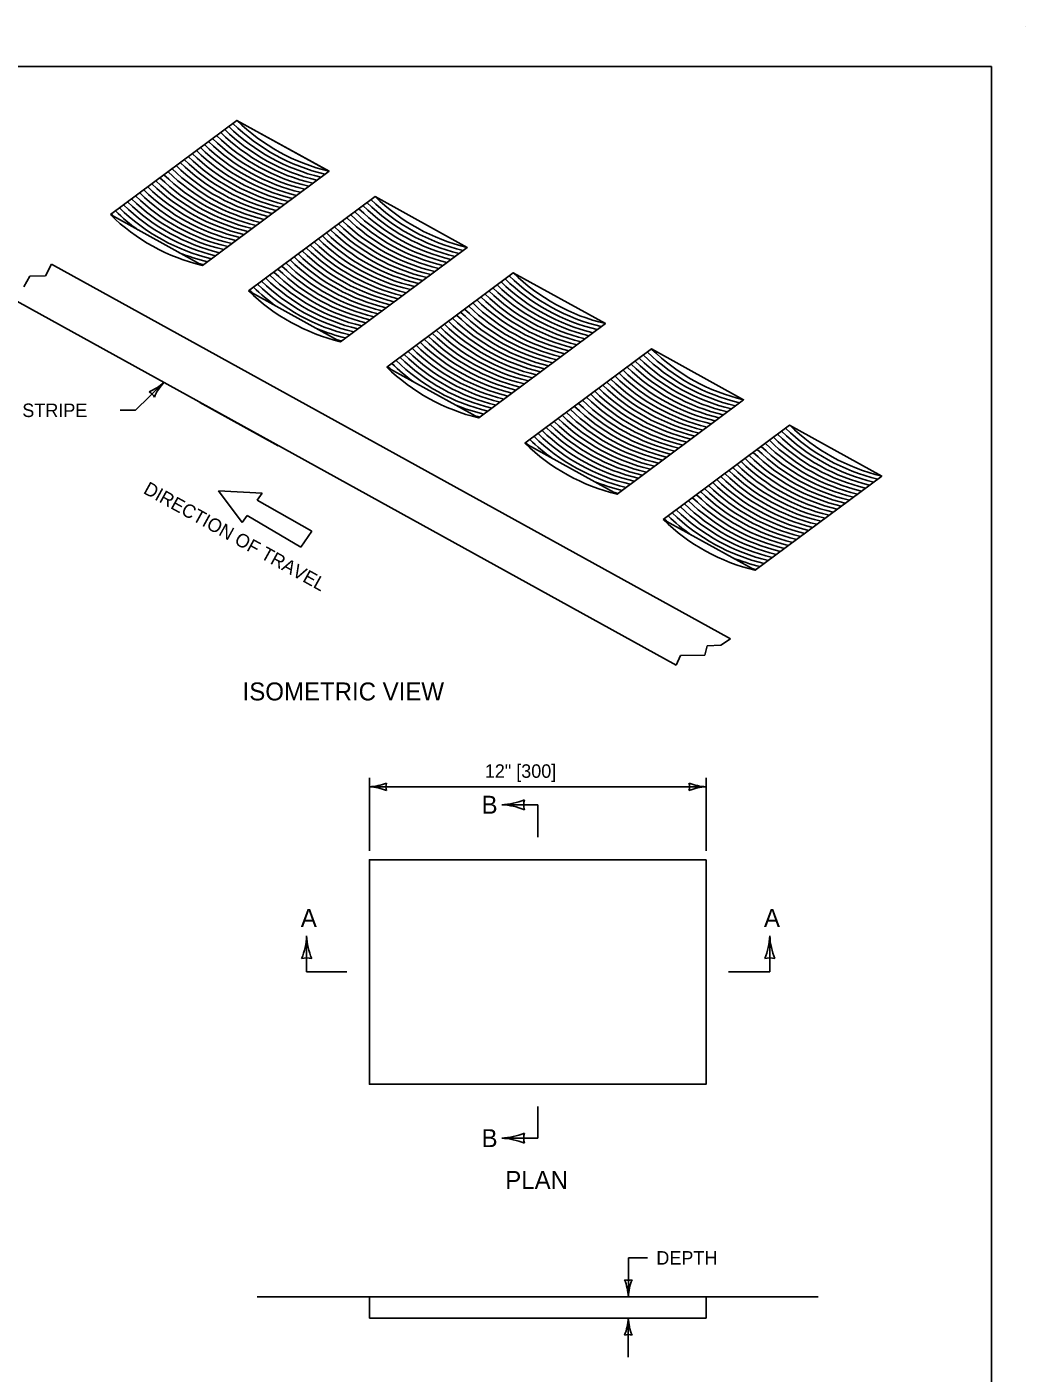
# Model space of a CAD drawing. Extents: x 49991.4 to 50021, y 49987.6 to 50011.4.
# Drawn here: x 50012.45 to 50016.9, y 49993.18 to 49999.18 of the extents above; entities that cross this region are included whole.
import ezdxf

# ---------------------------------------------------------------- set-up
doc = ezdxf.new("R2010")
doc.units = 0
for name, color, linetype in [('Level 1', 7, 'Continuous'), ('Level 2', 7, 'Continuous'), ('Level 3', 7, 'Continuous'), ('Level 4', 7, 'Continuous'), ('Level 6', 7, 'Continuous')]:
    doc.layers.add(name, color=color, linetype=linetype)

msp = doc.modelspace()

# ---------------------------------------------------------------- linework, layer by layer
at = {"layer": 'Level 1'}
for p, q in [((50016.9001, 49999.1756), (50016.9001, 49999.1756)), ((50013.7983, 49998.5328), (50013.3878, 49998.7591)), ((50014.4143, 49998.1935), (50014.0037, 49998.4198)), ((50012.5625, 49998.1179), (50012.5359, 49998.0661)), ((50015.5869, 49996.45), (50012.5625, 49998.1179)), ((50012.4655, 49998.065), (50012.4382, 49998.018)), ((50012.5359, 49998.0661), (50012.4655, 49998.065)), ((50015.03, 49997.8539), (50014.6195, 49998.0803)), ((50015.3448, 49996.3328), (50012.3203, 49998.0008)), ((50015.6458, 49997.5143), (50015.2353, 49997.7407)), ((50013.223, 49997.5029), (50013.5726, 49997.31)), ((50016.2616, 49997.1747), (50015.8511, 49997.4011)), ((50013.5002, 49997.0984), (50013.306, 49997.109)), ((50013.306, 49997.109), (50013.4121, 49996.9676)), ((50013.4787, 49997.0667), (50013.5002, 49997.0984)), ((50013.7217, 49996.9287), (50013.4787, 49997.0667)), ((50013.4121, 49996.9676), (50013.4333, 49996.9987)), ((50013.4333, 49996.9987), (50013.6726, 49996.8579)), ((50013.6726, 49996.8579), (50013.7217, 49996.9287)), ((50015.5869, 49996.45), (50015.5437, 49996.4217)), ((50015.3643, 49996.3756), (50015.3448, 49996.3328)), ((50015.4727, 49996.3764), (50015.3643, 49996.3756)), ((50015.4833, 49996.4185), (50015.4727, 49996.3764)), ((50015.5437, 49996.4217), (50015.4833, 49996.4185)), ((50013.9786, 49994.4652), (50015.4786, 49994.4652)), ((50013.4786, 49993.5182), (50015.9786, 49993.5182)), ((50013.9786, 49993.4232), (50013.9786, 49993.5182)), ((50015.4786, 49993.5182), (50015.4786, 49993.4232)), ((50013.9786, 49993.4232), (50015.4786, 49993.4232))]:
    msp.add_line(p, q, dxfattribs=at)
for points in [[(49999.3835, 49998.9992), (50016.7501, 49998.9992), (50016.7501, 49987.7988), (49999.3835, 49987.7988)], [(50012.8243, 49998.3392), (50013.2347, 49998.1128), (50013.7985, 49998.533), (50013.388, 49998.7593)], [(50013.44, 49997.9997), (50013.8504, 49997.7733), (50014.4143, 49998.1935), (50014.0037, 49998.4198)], [(50014.0558, 49997.6601), (50014.4662, 49997.4338), (50015.03, 49997.8539), (50014.6195, 49998.0803)], [(50014.6716, 49997.3205), (50015.082, 49997.0943), (50015.6458, 49997.5143), (50015.2353, 49997.7407)], [(50015.2874, 49996.9809), (50015.6978, 49996.7547), (50016.2616, 49997.1747), (50015.8511, 49997.4011)], [(50015.4786, 49995.4652), (50015.4786, 49994.4652), (50013.9786, 49994.4652), (50013.9786, 49995.4652)]]:
    msp.add_lwpolyline(points, close=True, dxfattribs=at)
for centre, radius, start, end in [((50013.9299, 49999.3336), 0.8786, 225.65161, 256.59181), ((50013.9479, 49999.3471), 0.8786, 225.6516, 256.59175), ((50013.966, 49999.3605), 0.8786, 225.65159, 256.59168), ((50013.984, 49999.374), 0.8786, 225.65158, 256.59161), ((50014.0019, 49999.3874), 0.8786, 225.65631, 256.59765), ((50014.0019, 49999.3874), 0.8786, 225.65548, 256.59848), ((50013.8577, 49999.2799), 0.8786, 225.65165, 256.59209), ((50013.8757, 49999.2933), 0.8786, 225.65164, 256.59202), ((50013.8938, 49999.3068), 0.8786, 225.65163, 256.59195), ((50013.9118, 49999.3202), 0.8786, 225.65162, 256.59188), ((50013.7675, 49999.2126), 0.8786, 225.6517, 256.59243), ((50013.7855, 49999.2261), 0.8786, 225.65169, 256.59236), ((50013.8036, 49999.2395), 0.8786, 225.65168, 256.59229), ((50013.8216, 49999.253), 0.8786, 225.65167, 256.59222), ((50013.8397, 49999.2664), 0.8786, 225.65166, 256.59216), ((50013.6953, 49999.1589), 0.8786, 225.65174, 256.5927), ((50013.7134, 49999.1723), 0.8786, 225.65173, 256.59264), ((50013.7314, 49999.1858), 0.8786, 225.65172, 256.59257), ((50013.7495, 49999.1992), 0.8786, 225.65171, 256.5925), ((50013.6051, 49999.0916), 0.8786, 225.65179, 256.59305), ((50013.6232, 49999.1051), 0.8786, 225.65178, 256.59298), ((50013.6412, 49999.1185), 0.8786, 225.65177, 256.59291), ((50013.6593, 49999.132), 0.8786, 225.65176, 256.59284), ((50013.6773, 49999.1454), 0.8786, 225.65175, 256.59277), ((50013.533, 49999.0379), 0.8786, 225.65183, 256.59332), ((50013.551, 49999.0513), 0.8786, 225.65182, 256.59325), ((50013.569, 49999.0647), 0.8786, 225.65181, 256.59318), ((50013.5871, 49999.0782), 0.8786, 225.6518, 256.59311), ((50014.5997, 49999.0345), 0.8786, 225.64828, 256.59228), ((50014.6178, 49999.0483), 0.8788, 225.66738, 256.61038), ((50014.6178, 49999.0483), 0.8788, 225.66738, 256.61038), ((50013.4608, 49998.9841), 0.8786, 225.65187, 234.15305), ((50013.4788, 49998.9975), 0.8786, 225.65186, 256.59352), ((50013.4969, 49999.011), 0.8786, 225.65185, 256.59346), ((50013.5149, 49999.0244), 0.8786, 225.65184, 256.59339), ((50014.5276, 49998.9807), 0.8786, 225.64832, 256.5919), ((50014.5456, 49998.9941), 0.8786, 225.64831, 256.592), ((50014.5637, 49999.0076), 0.8786, 225.6483, 256.59209), ((50014.5817, 49999.021), 0.8786, 225.64829, 256.59765), ((50013.4428, 49998.9706), 0.8786, 225.65188, 226.8839), ((50014.4374, 49998.9135), 0.8786, 225.64837, 256.59143), ((50014.4554, 49998.9269), 0.8786, 225.64836, 256.59153), ((50014.4735, 49998.9403), 0.8786, 225.64835, 256.59162), ((50014.4915, 49998.9538), 0.8786, 225.64834, 256.59172), ((50014.5095, 49998.9672), 0.8786, 225.64833, 256.59181), ((50014.3652, 49998.8597), 0.8786, 225.64841, 256.59106), ((50014.3832, 49998.8731), 0.8786, 225.6484, 256.59115), ((50014.4013, 49998.8866), 0.8786, 225.64839, 256.59124), ((50014.4193, 49998.9), 0.8786, 225.64838, 256.59134), ((50013.4608, 49998.9841), 0.8786, 247.95966, 256.59359), ((50014.275, 49998.7924), 0.8786, 225.64846, 256.59059), ((50014.293, 49998.8059), 0.8786, 225.64845, 256.59068), ((50014.3111, 49998.8193), 0.8786, 225.64844, 256.59077), ((50014.3291, 49998.8328), 0.8786, 225.64843, 256.59087), ((50014.3472, 49998.8462), 0.8786, 225.64842, 256.59096), ((50013.4428, 49998.9706), 0.8786, 255.29464, 256.59765), ((50014.2028, 49998.7387), 0.8786, 225.6485, 256.59021), ((50014.2209, 49998.7521), 0.8786, 225.64849, 256.5903), ((50014.2389, 49998.7656), 0.8786, 225.64848, 256.5904), ((50014.257, 49998.779), 0.8786, 225.64847, 256.59049), ((50014.1126, 49998.6714), 0.8786, 225.64855, 256.58974), ((50014.1307, 49998.6849), 0.8786, 225.64854, 256.58983), ((50014.1487, 49998.6983), 0.8786, 225.64853, 256.58993), ((50014.1668, 49998.7118), 0.8786, 225.64852, 256.59002), ((50014.1848, 49998.7252), 0.8786, 225.64851, 256.59012), ((50015.1975, 49998.6815), 0.8786, 225.6478, 256.59274), ((50015.2155, 49998.6949), 0.8786, 225.64762, 256.59289), ((50015.2338, 49998.7086), 0.8787, 225.65078, 256.59377), ((50015.2338, 49998.7086), 0.8787, 225.65078, 256.59377), ((50014.0585, 49998.6311), 0.8786, 225.64858, 226.8845), ((50014.0765, 49998.6446), 0.8786, 225.64857, 234.29264), ((50014.0946, 49998.658), 0.8786, 225.64856, 256.58965), ((50015.1073, 49998.6143), 0.8786, 225.6487, 256.59199), ((50015.1253, 49998.6277), 0.8786, 225.64852, 256.59214), ((50015.1434, 49998.6412), 0.8786, 225.64834, 256.59229), ((50015.1614, 49998.6546), 0.8786, 225.64816, 256.59244), ((50015.1794, 49998.668), 0.8786, 225.64798, 256.59259), ((50015.0351, 49998.5605), 0.8786, 225.64942, 256.59139), ((50015.0532, 49998.5739), 0.8786, 225.64924, 256.59154), ((50015.0712, 49998.5874), 0.8786, 225.64906, 256.59169), ((50015.0892, 49998.6008), 0.8786, 225.64888, 256.59184), ((50014.9449, 49998.4933), 0.8786, 225.65031, 256.59065), ((50014.963, 49998.5067), 0.8786, 225.65013, 256.5908), ((50014.981, 49998.5201), 0.8786, 225.64996, 256.59095), ((50014.999, 49998.5336), 0.8786, 225.64978, 256.5911), ((50015.0171, 49998.547), 0.8786, 225.6496, 256.59125), ((50014.0765, 49998.6446), 0.8786, 247.95966, 256.58955), ((50014.8727, 49998.4395), 0.8786, 225.65103, 256.59005), ((50014.8908, 49998.4529), 0.8786, 225.65085, 256.5902), ((50014.9088, 49998.4664), 0.8786, 225.65067, 256.59035), ((50014.9269, 49998.4798), 0.8786, 225.65049, 256.5905), ((50014.0585, 49998.6311), 0.8786, 255.34824, 256.58946), ((50014.7825, 49998.3723), 0.8786, 225.65193, 256.5893), ((50014.8006, 49998.3857), 0.8786, 225.65175, 256.58945), ((50014.8186, 49998.3991), 0.8786, 225.65157, 256.5896), ((50014.8367, 49998.4126), 0.8786, 225.65139, 256.58975), ((50014.8547, 49998.426), 0.8786, 225.65121, 256.5899), ((50014.7104, 49998.3185), 0.8786, 225.65265, 256.5887), ((50014.7284, 49998.3319), 0.8786, 225.65247, 256.58885), ((50014.7465, 49998.3454), 0.8786, 225.65229, 256.589), ((50014.7645, 49998.3588), 0.8786, 225.65211, 256.58915), ((50015.7772, 49998.315), 0.8786, 225.65081, 256.59498), ((50015.7952, 49998.3285), 0.8786, 225.65063, 256.59534), ((50015.8133, 49998.3419), 0.8786, 225.65045, 256.59571), ((50015.8313, 49998.3554), 0.8786, 225.65027, 256.59608), ((50015.8496, 49998.369), 0.8787, 225.65078, 256.59377), ((50015.8496, 49998.369), 0.8787, 225.65078, 256.59377), ((50014.6743, 49998.2916), 0.8786, 225.653, 226.8993), ((50014.6923, 49998.305), 0.8786, 225.65283, 234.17234), ((50015.705, 49998.2613), 0.8786, 225.65153, 256.5935), ((50015.7231, 49998.2747), 0.8786, 225.65135, 256.59387), ((50015.7411, 49998.2882), 0.8786, 225.65117, 256.59424), ((50015.7592, 49998.3016), 0.8786, 225.65099, 256.59461), ((50015.6148, 49998.194), 0.8786, 225.65242, 256.59167), ((50015.6329, 49998.2075), 0.8786, 225.65224, 256.59203), ((50015.6509, 49998.2209), 0.8786, 225.65206, 256.5924), ((50015.669, 49998.2344), 0.8786, 225.65188, 256.59277), ((50015.687, 49998.2478), 0.8786, 225.6517, 256.59314), ((50015.5427, 49998.1403), 0.8786, 225.65314, 256.59019), ((50015.5607, 49998.1537), 0.8786, 225.65296, 256.59056), ((50015.5788, 49998.1672), 0.8786, 225.65278, 256.59093), ((50015.5968, 49998.1806), 0.8786, 225.6526, 256.5913), ((50014.6923, 49998.305), 0.8786, 248.08181, 256.58855), ((50015.4525, 49998.073), 0.8786, 225.65404, 256.58835), ((50015.4705, 49998.0865), 0.8786, 225.65386, 256.58872), ((50015.4885, 49998.0999), 0.8786, 225.65368, 256.58909), ((50015.5066, 49998.1134), 0.8786, 225.6535, 256.58946), ((50015.5246, 49998.1268), 0.8786, 225.65332, 256.58983), ((50014.6743, 49998.2916), 0.8786, 255.35485, 256.5884), ((50015.3803, 49998.0193), 0.8786, 225.65475, 256.58688), ((50015.3983, 49998.0327), 0.8786, 225.65457, 256.58725), ((50015.4164, 49998.0461), 0.8786, 225.6544, 256.58762), ((50015.4344, 49998.0596), 0.8786, 225.65422, 256.58799), ((50016.4471, 49998.0158), 0.8786, 225.65292, 256.59949), ((50016.4654, 49998.0294), 0.8787, 225.65078, 256.59377), ((50016.4654, 49998.0294), 0.8787, 225.65078, 256.59377), ((50015.2901, 49997.952), 0.8786, 225.65565, 226.90989), ((50015.3081, 49997.9655), 0.8786, 225.65547, 234.18187), ((50015.3262, 49997.9789), 0.8786, 225.65529, 256.58578), ((50015.3442, 49997.9924), 0.8786, 225.65511, 256.58615), ((50015.3623, 49998.0058), 0.8786, 225.65493, 256.58652), ((50016.375, 49997.9621), 0.8786, 225.65363, 256.59802), ((50016.393, 49997.9755), 0.8786, 225.65345, 256.59839), ((50016.411, 49997.9889), 0.8786, 225.65327, 256.59875), ((50016.4291, 49998.0024), 0.8786, 225.6531, 256.59912), ((50016.2848, 49997.8948), 0.8786, 225.65453, 256.59618), ((50016.3028, 49997.9083), 0.8786, 225.65435, 256.59655), ((50016.3208, 49997.9217), 0.8786, 225.65417, 256.59691), ((50016.3389, 49997.9352), 0.8786, 225.65399, 256.59728), ((50016.3569, 49997.9486), 0.8786, 225.65381, 256.59765), ((50016.2126, 49997.841), 0.8786, 225.65525, 256.59471), ((50016.2306, 49997.8545), 0.8786, 225.65507, 256.59507), ((50016.2487, 49997.8679), 0.8786, 225.65489, 256.59544), ((50016.2667, 49997.8814), 0.8786, 225.65471, 256.59581), ((50015.3081, 49997.9655), 0.8786, 248.09369, 256.58541), ((50016.1224, 49997.7738), 0.8786, 225.65615, 256.59287), ((50016.1404, 49997.7873), 0.8786, 225.65597, 256.59323), ((50016.1585, 49997.8007), 0.8786, 225.65579, 256.5936), ((50016.1765, 49997.8142), 0.8786, 225.65561, 256.59397), ((50016.1946, 49997.8276), 0.8786, 225.65543, 256.59434), ((50015.2901, 49997.952), 0.8786, 255.36568, 256.58504), ((50016.0502, 49997.72), 0.8786, 225.65686, 256.5914), ((50016.0683, 49997.7335), 0.8786, 225.65668, 256.59176), ((50016.0863, 49997.7469), 0.8786, 225.6565, 256.59213), ((50016.1043, 49997.7604), 0.8786, 225.65632, 256.5925), ((50015.96, 49997.6528), 0.8786, 225.65776, 256.58956), ((50015.9781, 49997.6663), 0.8786, 225.65758, 256.58992), ((50015.9961, 49997.6797), 0.8786, 225.6574, 256.59029), ((50016.0141, 49997.6932), 0.8786, 225.65722, 256.59066), ((50016.0322, 49997.7066), 0.8786, 225.65704, 256.59103), ((50015.9059, 49997.6125), 0.8786, 225.6583, 226.92151), ((50015.9239, 49997.6259), 0.8786, 225.65812, 234.20549), ((50015.942, 49997.6394), 0.8786, 225.65794, 256.58919), ((50015.9239, 49997.6259), 0.8786, 248.07008, 256.58882), ((50015.9059, 49997.6125), 0.8786, 255.35405, 256.58845)]:
    msp.add_arc(centre, radius, start, end, dxfattribs=at)
at = {"layer": 'Level 3'}
for p, q in [((50012.9366, 49997.4675), (50013.0627, 49997.5914)), ((50012.8686, 49997.4675), (50012.9366, 49997.4675)), ((50013.9786, 49995.5052), (50013.9786, 49995.8303)), ((50015.4786, 49995.5052), (50015.4786, 49995.8303)), ((50013.9786, 49995.7903), (50015.4786, 49995.7903)), ((50015.1323, 49993.6916), (50015.2171, 49993.6916)), ((50015.1323, 49993.5182), (50015.1323, 49993.6916)), ((50015.132, 49993.2498), (50015.132, 49993.4232))]:
    msp.add_line(p, q, dxfattribs=at)
for centre, radius, start, end in [((50012.9134, 49997.7562), 0.2223, 291.97454, 312.15805), ((50013.234, 49997.4335), 0.233, 137.34584, 156.59569), ((50012.9712, 49997.5015), 0.0548, 26.65735, 62.37971), ((50013.9671, 49996.023), 0.233, 272.82731, 292.07716), ((50013.9694, 49995.5682), 0.2223, 67.45601, 87.63952), ((50014.1068, 49995.7903), 0.0548, 162.13882, 197.86118), ((50015.4878, 49996.0124), 0.2223, 247.45601, 267.63952), ((50015.3504, 49995.7903), 0.0548, 342.13882, 17.86118), ((50015.4901, 49995.5576), 0.233, 92.82731, 112.07716), ((50014.5527, 49996.0206), 0.3107, 272.82731, 292.07716), ((50014.5558, 49995.4141), 0.2964, 67.45601, 87.63952), ((50014.739, 49995.7103), 0.073, 162.13882, 197.86118), ((50013.4027, 49995.1383), 0.2964, 337.45601, 357.63952), ((50014.0092, 49995.1414), 0.3107, 182.82731, 202.07716), ((50015.4664, 49995.1383), 0.2964, 337.45601, 357.63952), ((50016.0729, 49995.1414), 0.3107, 182.82731, 202.07716), ((50013.6989, 49994.9551), 0.073, 72.13882, 107.86118), ((50015.7626, 49994.9551), 0.073, 72.13882, 107.86118), ((50014.5527, 49994.5352), 0.3107, 272.82731, 292.07716), ((50014.5558, 49993.9287), 0.2964, 67.45601, 87.63952), ((50014.739, 49994.2249), 0.073, 162.13882, 197.86118), ((50015.1323, 49993.6464), 0.0548, 252.13882, 287.86118), ((50014.8996, 49993.5067), 0.233, 2.82731, 22.07716), ((50015.3544, 49993.5091), 0.2223, 157.45601, 177.63952), ((50014.9099, 49993.4324), 0.2223, 337.45601, 357.63952), ((50015.3647, 49993.4347), 0.233, 182.82731, 202.07716), ((50015.132, 49993.295), 0.0548, 72.13882, 107.86118)]:
    msp.add_arc(centre, radius, start, end, dxfattribs=at)
at = {"layer": 'Level 4'}
for centre, radius, start, end in [((50013.4385, 49998.9673), 0.8785, 225.64487, 256.58787), ((50014.0542, 49998.6278), 0.8785, 225.64487, 256.58787), ((50014.6698, 49998.2883), 0.8784, 225.65558, 256.59857), ((50015.2855, 49997.9487), 0.8783, 225.66628, 256.60928), ((50015.9013, 49997.6091), 0.8783, 225.66628, 256.60928)]:
    msp.add_arc(centre, radius, start, end, dxfattribs=at)
at = {"layer": 'Level 6'}
for p, q in [((50014.7286, 49995.7103), (50014.568, 49995.7103)), ((50014.7286, 49995.5652), (50014.7286, 49995.7103)), ((50013.6989, 49994.9652), (50013.6989, 49995.1261)), ((50015.7626, 49994.9652), (50015.7626, 49995.1261)), ((50013.6989, 49994.9652), (50013.8786, 49994.9652)), ((50015.5786, 49994.9652), (50015.7626, 49994.9652)), ((50014.7286, 49994.3652), (50014.7286, 49994.2249)), ((50014.7286, 49994.2249), (50014.568, 49994.2249))]:
    msp.add_line(p, q, dxfattribs=at)

# ---------------------------------------------------------------- texts
at = {"layer": 'Level 2'}
for s, height, p in [('LANE EDGE STRIPE', 0.06, (50011.9503, 49997.4375)), ('ISOMETRIC VIEW', 0.08, (50013.4135, 49996.175)), ('12" [300]', 0.06, (50014.4927, 49995.8303)), ('B', 0.08, (50014.4782, 49995.6703)), ('A', 0.08, (50013.6728, 49995.1661)), ('A', 0.08, (50015.7365, 49995.1661)), ('B', 0.08, (50014.4782, 49994.1849)), ('PLAN', 0.08, (50014.5838, 49993.9985)), ('DEPTH', 0.06, (50015.2571, 49993.6616))]:
    msp.add_text(s, height=height, dxfattribs=at).set_placement(p)
msp.add_text('DIRECTION OF TRAVEL', height=0.06, rotation=331.01456, dxfattribs=at).set_placement((50012.9671, 49997.1))

doc.saveas('drawing.dxf')
